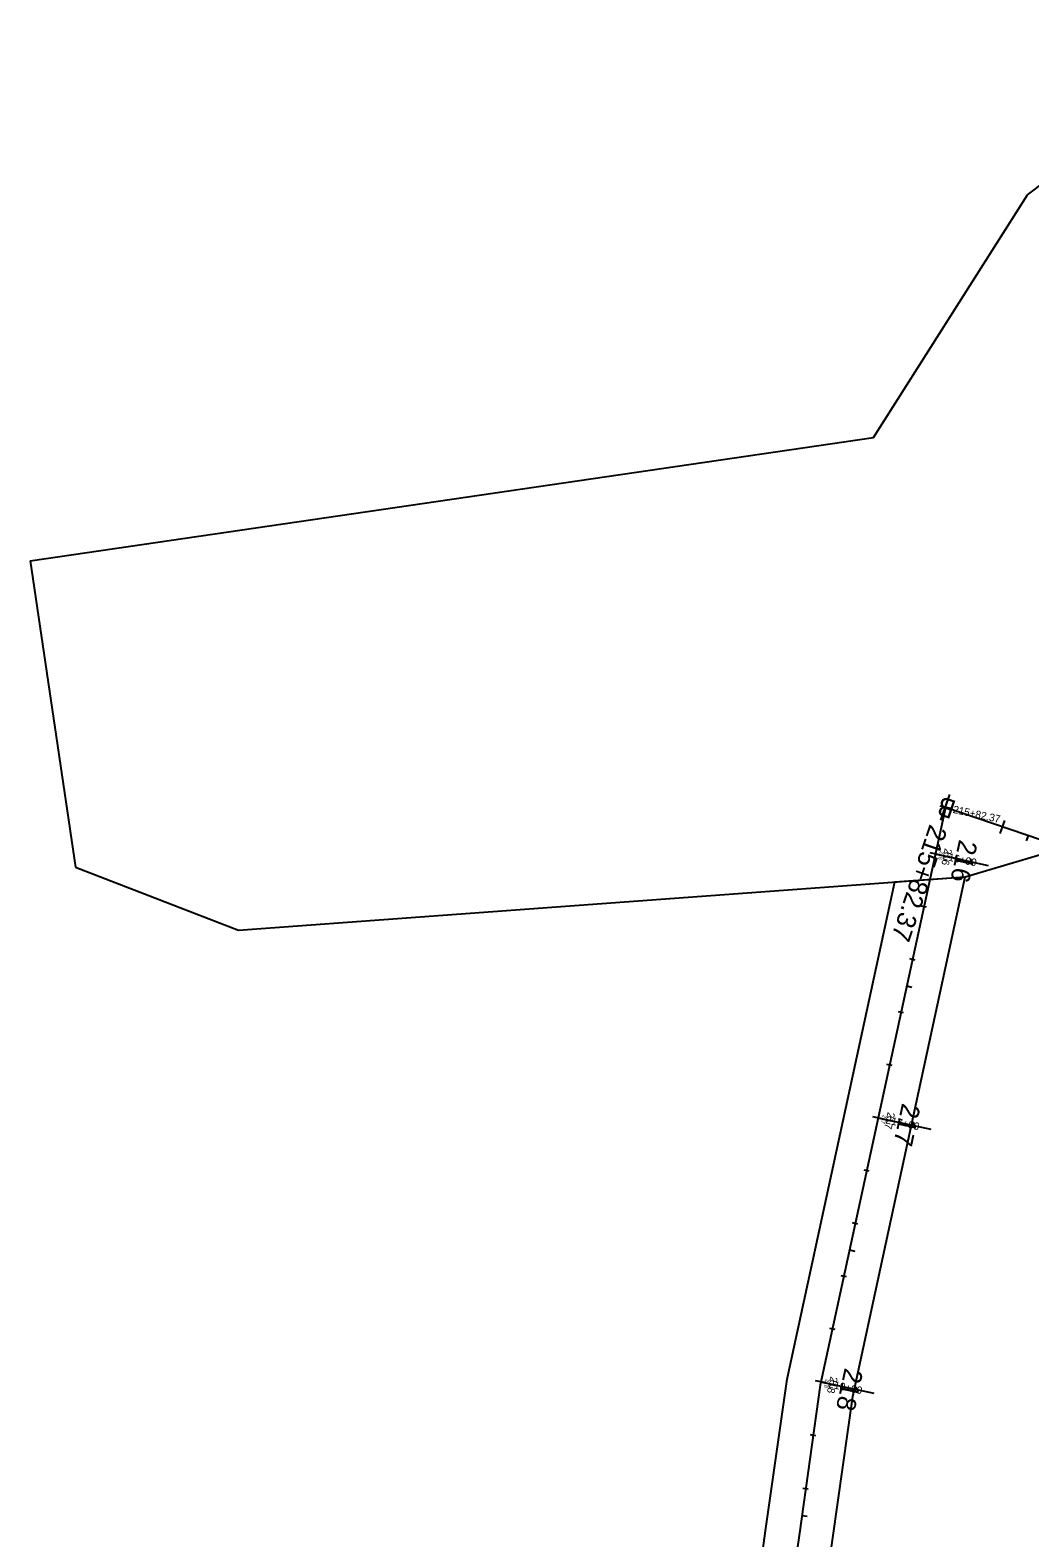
# Model space of a CAD drawing. Extents: x 1823824 to 1861612, y 706975 to 726130.
# Drawn here: x 1824112 to 1824483, y 711164 to 711723 of the extents above; entities that cross this region are included whole.
import ezdxf

# ---------------------------------------------------------------- set-up
doc = ezdxf.new("R2010")
doc.units = 0
for name, color, linetype in [('DR_X_Flood_Boundary', 7, 'Continuous'), ('GE_X_CL_10', 7, 'Continuous'), ('GE_X_CL_100', 7, 'Continuous'), ('GE_X_CL_20', 7, 'Continuous'), ('GE_X_CL_200', 7, 'Continuous'), ('GE_X_CL_50', 7, 'Continuous'), ('RW_X_Esmt_FL', 7, 'Continuous'), ('SC_Scratch5', 7, 'Continuous'), ('SC_Scratch6', 7, 'Continuous')]:
    doc.layers.add(name, color=color, linetype=linetype)

msp = doc.modelspace()

# ---------------------------------------------------------------- linework, layer by layer
at = {"layer": 'DR_X_Flood_Boundary'}
for p, q in [((1824451.24, 711434.9), (1824404.89, 711221.03)), ((1824486.83, 711422.71), (1824451.24, 711434.9)), ((1824404.89, 711221.03), (1824397.16, 711166.2)), ((1824397.16, 711166.2), (1824376.93, 711022.79))]:
    msp.add_line(p, q, dxfattribs=at)
at = {"layer": 'GE_X_CL_10'}
for p, q in [((1824481.86, 711424.41), (1824481.54, 711423.46)), ((1824447.5, 711417.67), (1824448.48, 711417.46)), ((1824436.91, 711368.81), (1824437.89, 711368.6)), ((1824426.32, 711319.94), (1824427.3, 711319.73)), ((1824415.74, 711271.08), (1824416.71, 711270.86)), ((1824405.15, 711222.21), (1824406.12, 711222)), ((1824398.08, 711172.72), (1824399.07, 711172.58))]:
    msp.add_line(p, q, dxfattribs=at)
at = {"layer": 'GE_X_CL_100'}
for p, q in [((1824447.5, 711417.67), (1824457.28, 711415.56)), ((1824426.32, 711319.94), (1824436.1, 711317.82)), ((1824405.15, 711222.21), (1824414.92, 711220.09))]:
    msp.add_line(p, q, dxfattribs=at)
at = {"layer": 'GE_X_CL_20'}
for p, q in [((1824481.86, 711424.41), (1824481.21, 711422.52)), ((1824447.5, 711417.67), (1824449.46, 711417.25)), ((1824436.91, 711368.81), (1824438.87, 711368.38)), ((1824426.32, 711319.94), (1824428.28, 711319.52)), ((1824415.74, 711271.08), (1824417.69, 711270.65)), ((1824405.15, 711222.21), (1824407.1, 711221.79)), ((1824398.08, 711172.72), (1824400.06, 711172.44))]:
    msp.add_line(p, q, dxfattribs=at)
at = {"layer": 'GE_X_CL_200'}
for p, q in [((1824447.5, 711417.67), (1824467.05, 711413.44)), ((1824426.32, 711319.94), (1824445.87, 711315.71)), ((1824405.15, 711222.21), (1824424.69, 711217.98))]:
    msp.add_line(p, q, dxfattribs=at)
at = {"layer": 'GE_X_CL_50'}
for p, q in [((1824447.5, 711417.67), (1824452.39, 711416.62)), ((1824426.32, 711319.94), (1824431.21, 711318.88)), ((1824405.15, 711222.21), (1824410.03, 711221.15))]:
    msp.add_line(p, q, dxfattribs=at)
at = {"layer": 'RW_X_Esmt_FL'}
for p, q in [((1824481.66, 711661.64), (1824561.76, 711722.66)), ((1824424.62, 711571.89), (1824481.66, 711661.64)), ((1824112.22, 711526.17), (1824424.62, 711571.89)), ((1824112.22, 711526.17), (1824128.99, 711412.72)), ((1824458.62, 711409.24), (1824605.52, 711452.44)), ((1824128.99, 711412.72), (1824189.46, 711389.49)), ((1824189.46, 711389.49), (1824458.62, 711409.24)), ((1824416.92, 711216.83), (1824458.62, 711409.24)), ((1824432.47, 711407.32), (1824458.62, 711409.24)), ((1824392.58, 711223.23), (1824432.47, 711407.32)), ((1824384.78, 711167.95), (1824392.58, 711223.23)), ((1824409.54, 711164.46), (1824416.92, 711216.83)), ((1824361.71, 711004.36), (1824384.78, 711167.95)), ((1824391.54, 711036.88), (1824409.54, 711164.46))]:
    msp.add_line(p, q, dxfattribs=at)
at = {"layer": 'SC_Scratch5'}
for points in [[(1824453.19, 711434.48), (1824449.28, 711435.33)], [(1824449.62, 711430.17), (1824452.86, 711439.63)], [(1824450.43, 711432.54), (1824452.05, 711437.27)], [(1824452.67, 711431.77), (1824454.29, 711436.5)], [(1824452.21, 711434.69), (1824450.26, 711435.12)], [(1824471.59, 711425.28), (1824473.21, 711430.01)], [(1824449.46, 711417.25), (1824445.55, 711418.1)], [(1824444.24, 711397.92), (1824442.29, 711398.34)], [(1824440.01, 711378.37), (1824438.05, 711378.79)], [(1824435.77, 711358.82), (1824433.82, 711359.25)], [(1824431.54, 711339.28), (1824429.58, 711339.7)], [(1824428.28, 711319.52), (1824424.37, 711320.37)], [(1824423.07, 711300.18), (1824421.11, 711300.61)], [(1824418.83, 711280.64), (1824416.88, 711281.06)], [(1824414.6, 711261.09), (1824412.64, 711261.52)], [(1824410.36, 711241.55), (1824408.41, 711241.97)], [(1824407.1, 711221.79), (1824403.19, 711222.63)], [(1824403.26, 711202.28), (1824401.28, 711202.56)], [(1824400.46, 711182.48), (1824398.48, 711182.76)]]:
    msp.add_lwpolyline(points, dxfattribs=at)

# ---------------------------------------------------------------- texts
at = {"layer": 'GE_X_CL_10'}
for s, p in [('216', (1824449.28, 711418.79)), ('217', (1824428.11, 711321.08)), ('218', (1824406.92, 711223.29))]:
    msp.add_text(s, height=1.4, rotation=257.7735, dxfattribs=at).set_placement(p)
at = {"layer": 'GE_X_CL_20'}
for s, p in [('216', (1824451.06, 711419.9)), ('217', (1824429.89, 711322.23)), ('218', (1824408.69, 711224.38))]:
    msp.add_text(s, height=2.8, rotation=257.7735, dxfattribs=at).set_placement(p)
at = {"layer": 'GE_X_CL_50'}
for s, p in [('216', (1824456.38, 711423.25)), ('217', (1824435.24, 711325.65)), ('218', (1824413.99, 711227.62))]:
    msp.add_text(s, height=7, rotation=257.7735, dxfattribs=at).set_placement(p)
at = {"layer": 'SC_Scratch5'}
for s, height, rotation, p in [('215+82.37', 2.8, 347.7735, (1824453.87, 711432.9)), ('215+82.37', 7, 251.081, (1824445.49, 711428.94)), ('216+00', 2.8, 347.7735, (1824450.14, 711415.67)), ('217+00', 2.8, 347.7735, (1824428.96, 711317.94)), ('218+00', 2.8, 347.7735, (1824407.78, 711220.21))]:
    msp.add_text(s, height=height, rotation=rotation, dxfattribs=at).set_placement(p)
at = {"layer": 'SC_Scratch6'}
msp.add_text('B', height=7, rotation=161.081, dxfattribs=at).set_placement((1824455.68, 711437.08))

doc.saveas('drawing.dxf')
